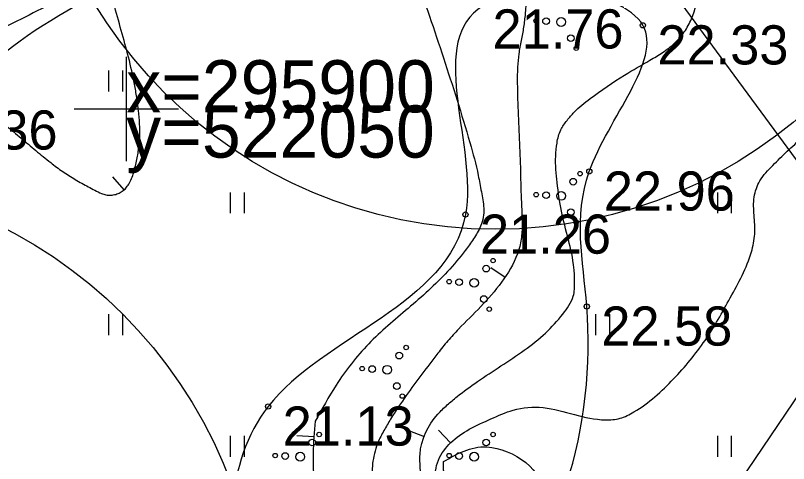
# Model space of a CAD drawing. Extents: x 521824 to 524158, y 294774 to 296228.
# Drawn here: x 522046.82 to 522069.04, y 295889.8 to 295902.69 of the extents above; entities that cross this region are included whole.
import ezdxf

# ---------------------------------------------------------------- set-up
doc = ezdxf.new("R2010")
doc.units = 0
for name, color, linetype in [('CELI_TAKA_####_####_#', 7, 'Continuous'), ('GEOD_ELEM_####_####_#', 7, 'Continuous'), ('GEOD_KORD_####_TKST_#', 7, 'Continuous'), ('Geolite Projekts', 7, 'Continuous'), ('GL Aizsargjoslas', 7, 'Continuous'), ('RELJ_AATZ_####_TKST_#', 7, 'Continuous'), ('RELJ_ELEM_####_####_#', 7, 'Continuous'), ('RELJ_HORZ_PAMT_####_#', 7, 'Continuous'), ('RELJ_HORZ_RESN_####_#', 7, 'Continuous'), ('RELJ_NOGA_####_####_#', 7, 'Continuous'), ('RELJ_NOGL_####_####_#', 7, 'Continuous'), ('TERT_ELEM_####_####_#', 7, 'Continuous'), ('TERT_KONT_####_####_#', 7, 'Continuous')]:
    doc.layers.add(name, color=color, linetype=linetype)

msp = doc.modelspace()

# ---------------------------------------------------------------- linework, layer by layer
at = {"layer": 'CELI_TAKA_####_####_#'}
msp.add_lwpolyline([(522095.856, 295905.56700000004), (522084.37100000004, 295904.45), (522075.74700000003, 295894.91500000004), (522069.03400000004, 295885.9050000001), (522061.956, 295874.973), (522056.367, 295864.379), (522051.5294335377, 295852.1437104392), (522046.912, 295851.297), (522038.77300000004, 295857.478), (522034.27400000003, 295863.827), (522038.98455083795, 295867.1660796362), (522042.3269003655, 295865.914968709), (522049.35500000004, 295864.324), (522054.37200000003, 295869.372), (522059.47900000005, 295876.809), (522066.34400000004, 295887.376), (522073.29600000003, 295897.65400000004), (522079.21, 295907.668), (522079.60400000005, 295917.159)], dxfattribs=at)
at = {"layer": 'GEOD_ELEM_####_####_#'}
for p, q in [((522050, 295901.5), (522050, 295900)), ((522048.5, 295900), (522050, 295900)), ((522050, 295900), (522050, 295898.5)), ((522050, 295900), (522051.5, 295900))]:
    msp.add_line(p, q, dxfattribs=at)
at = {"layer": 'Geolite Projekts'}
for centre in [(522060.6062488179, 295910.0052488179), (522040.37824881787, 295884.5782488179)]:
    msp.add_circle(centre, 13.465789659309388, dxfattribs=at)
at = {"layer": 'GL Aizsargjoslas'}
msp.add_lwpolyline([(522131.42829998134, 295816.08118555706), (522115.4941642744, 295836.89638272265), (522093.2463759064, 295865.95927699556), (522070.6576329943, 295896.65064863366), (522048.0688900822, 295927.34202027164), (522034.2954443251, 295950.9093556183), (522016.4452583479, 295981.4522804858), (522014.1669435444, 295985.3506375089), (522007.1170540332, 295997.9066058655), (522041.3600169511, 296024.30747637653), (522061.8608109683, 296026.336216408), (522066.44900074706, 296014.80384880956), (522085.297555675, 295982.5526443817), (522098.68966425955, 295959.6378037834), (522141.23362409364, 295901.9807230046), (522163.3093357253, 295873.1426172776), (522185.385047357, 295844.30451155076), (522186.60753180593, 295842.8705587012), (522172.84800000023, 295833.39200000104), (522161.56349999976, 295826.06900000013), (522160.80220084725, 295825.5718620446), (522154.44700000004, 295832.01500000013)], close=True, dxfattribs=at)
at = {"layer": 'RELJ_ELEM_####_####_#'}
for centre in [(522064.85000000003, 295902.40400000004), (522063.309, 295898.202), (522059.75, 295896.963), (522063.237, 295894.32), (522054.07800000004, 295891.445)]:
    msp.add_circle(centre, 0.075, dxfattribs=at)
at = {"layer": 'RELJ_HORZ_PAMT_####_#'}
for p, q in [((522049.60648515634, 295898.0477462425), (522049.9331036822, 295897.66916951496)), ((522054.9032718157, 295890.6113446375), (522055.4021474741, 295890.57783229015)), ((522058.0958806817, 295890.76675691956), (522058.5617377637, 295890.5851607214)), ((522058.9771039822, 295890.76097983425), (522059.31931511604, 295890.39643691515))]:
    msp.add_line(p, q, dxfattribs=at)
for points in [[(522066.2584823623, 295871.9491597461), (522065.9265126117, 295872.02069348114), (522065.52187982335, 295872.1924293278), (522064.7111958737, 295872.77815327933), (522063.9034044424, 295873.5790320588), (522063.5023873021, 295874.01971144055), (522063.1042459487, 295874.4656478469), (522062.71785695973, 295875.16654893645), (522062.57713892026, 295875.4946600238), (522062.27065971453, 295876.0108950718), (522061.9020967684, 295876.4975825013), (522061.55203381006, 295876.9935582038), (522061.30105456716, 295877.5376580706), (522061.20400779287, 295877.93591094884), (522061.12801898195, 295878.33525191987), (522061.0351401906, 295879.1357661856), (522061.0142680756, 295879.93633695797), (522061.05725251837, 295880.73410032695), (522061.2405002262, 295882.3468136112), (522061.4726604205, 295883.9570245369), (522061.59669191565, 295884.54701605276), (522061.5847127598, 295884.58544792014), (522061.17685574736, 295885.2867575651), (522060.72233918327, 295885.9348866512), (522060.2601026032, 295886.5684557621), (522059.82908554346, 295887.2260854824), (522059.0920299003, 295888.55811252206), (522058.89348460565, 295889.2513533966), (522058.8913293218, 295889.5862413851), (522058.97472722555, 295889.90624515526), (522059.32943879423, 295890.4058551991), (522059.8583838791, 295890.78845924), (522060.4810182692, 295891.08831341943), (522061.11679775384, 295891.3396738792), (522061.9816911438, 295891.4141705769), (522062.8825577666, 295891.21225084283), (522063.7697265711, 295891.0611807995), (522064.1926520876, 295891.1069850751), (522064.5935265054, 295891.2882265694), (522065.73111615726, 295892.2383905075), (522066.63585033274, 295893.34363634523), (522067.3630420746, 295894.5711369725), (522067.9680044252, 295895.88806527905), (522068.0658538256, 295896.40279857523), (522068.04657160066, 295896.9434330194), (522068.0499213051, 295897.4675584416), (522068.21566649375, 295897.9327646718), (522068.58369240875, 295898.3767775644), (522068.99960998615, 295898.782723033), (522069.42179390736, 295899.1843208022), (522069.8086188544, 295899.61529059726), (522071.07609156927, 295901.3045079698), (522072.2197685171, 295903.14131751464), (522073.0777767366, 295905.1256097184), (522073.6055682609, 295907.1854540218), (522073.837089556, 295909.2646973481), (522073.85235713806, 295910.2940458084), (522073.8062870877, 295911.3071866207), (522073.4235574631, 295912.99914973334), (522073.02667042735, 295913.81930856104), (522072.479111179, 295914.61778212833), (522071.01685177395, 295916.0448324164), (522069.31251789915, 295917.0118651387), (522068.5372975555, 295917.2378305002), (522065.5425407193, 295917.72990654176), (522064.0452324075, 295917.74536597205), (522063.3144481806, 295917.64344913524), (522062.6023781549, 295917.4486243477), (522062.2001250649, 295917.20845970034), (522060.8816914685, 295916.59798905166)], [(522059.84382235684, 295885.48121856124), (522059.8438223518, 295885.4812185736), (522059.78676631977, 295885.6171710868), (522058.8865142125, 295887.8562219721), (522058.55276315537, 295888.9834516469), (522058.46311323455, 295889.53502410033), (522058.4436111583, 295889.80605367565), (522058.4432829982, 295890.0732469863), (522058.95354503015, 295891.22221891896), (522059.2266140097, 295891.4889343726), (522059.5078144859, 295891.7280506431), (522060.0974200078, 295892.16235402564), (522061.4403651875, 295893.0655420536), (522062.05069449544, 295893.5569964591), (522062.5478378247, 295894.10367275), (522062.84795303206, 295894.6148813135), (522062.8876709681, 295895.02128771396), (522062.86697334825, 295895.42851699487), (522062.7095877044, 295896.24487815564), (522062.5063086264, 295897.06283271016), (522062.3876486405, 295897.88124857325), (522062.34300690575, 295898.6402559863), (522062.38142149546, 295899.0201946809), (522062.4892913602, 295899.3960738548), (522062.67100015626, 295899.6700522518), (522062.87542367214, 295899.9064522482), (522063.33430111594, 295900.2977858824), (522064.3253814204, 295900.9734696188), (522065.0535739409, 295901.4006113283), (522065.4168611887, 295901.62440442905), (522065.59205733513, 295901.74880483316), (522065.7622515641, 295901.8909530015), (522066.0402461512, 295902.2124144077), (522066.24466940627, 295902.5881278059), (522066.4460868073, 295903.44091490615), (522066.27945845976, 295904.74326254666), (522066.11219937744, 295905.1221606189), (522065.4824909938, 295906.23163838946), (522064.81863151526, 295907.3324170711), (522064.15650249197, 295908.43747979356), (522063.5319854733, 295909.5598096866), (522062.8487309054, 295910.87969144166), (522062.23551999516, 295912.2254142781), (522061.55132910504, 295913.5372971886), (522060.6551345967, 295914.7556591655)], [(522056.1793664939, 295908.1153325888), (522056.48434317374, 295907.6743405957), (522056.8475368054, 295907.0795841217), (522057.17609128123, 295906.4660634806), (522057.4766860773, 295905.8230094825), (522057.76204092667, 295905.1745785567), (522058.2862568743, 295903.85904208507), (522058.71639752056, 295902.66520022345), (522059.118007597, 295901.46666925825), (522059.876249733, 295899.0317423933), (522060.11747807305, 295898.0904908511), (522060.20674188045, 295897.61826545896), (522060.27568828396, 295897.14600863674), (522060.18688952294, 295896.63185604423), (522060.09080228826, 295896.43995465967), (522059.9849630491, 295896.2639437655), (522059.74596148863, 295895.9336084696), (522059.2350731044, 295895.323283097), (522058.0985815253, 295894.2628950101), (522056.967747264, 295893.243683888), (522056.03290279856, 295892.0586418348), (522055.4318217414, 295891.019573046)], [(522044.3960820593, 295900.93691802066), (522044.4961399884, 295900.8916618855), (522044.8780289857, 295900.71492382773), (522045.2798363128, 295900.47416145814), (522046.1231182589, 295899.85556856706), (522046.5540807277, 295899.51268228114), (522046.9768135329, 295899.1602485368), (522047.39885349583, 295898.80536858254), (522047.827737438, 295898.45514366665), (522048.17397656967, 295898.2006330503), (522048.53616659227, 295897.970216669), (522048.9093562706, 295897.7610938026), (522049.09852871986, 295897.6636422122), (522049.2885943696, 295897.5704637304), (522049.4174768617, 295897.5294679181), (522049.55699419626, 295897.5208775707), (522049.69695640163, 295897.54360238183), (522049.82717350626, 295897.5965520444), (522049.93918509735, 295897.6744915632), (522050.03092400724, 295897.77483245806), (522050.11421739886, 295897.91129787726), (522050.18428589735, 295898.08160530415), (522050.28305070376, 295898.4529787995), (522050.3526554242, 295898.8248105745), (522050.38413350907, 295899.56810806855), (522050.35036100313, 295899.9499198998), (522050.301222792, 295900.33172656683), (522050.2371131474, 295900.7133025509), (522050.15842634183, 295901.09442233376), (522049.9618199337, 295901.8739762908), (522049.74695353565, 295902.6432265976), (522049.54332001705, 295903.41224045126), (522049.3804122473, 295904.1910850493)], [(522055.4318217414, 295891.019573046), (522055.37014606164, 295890.1014488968), (522055.4470548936, 295888.9609942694), (522055.7296555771, 295887.83428687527), (522056.06387243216, 295886.7113670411), (522056.2956297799, 295885.5822750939), (522056.3400053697, 295884.7079058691), (522056.29896105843, 295883.8276911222), (522056.21917381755, 295882.9659028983), (522056.0627431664, 295882.1126921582), (522055.74228698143, 295881.31167885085), (522055.4932424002, 295880.9443774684), (522055.34173727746, 295880.77141356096), (522055.17042313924, 295880.6064829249), (522053.57967248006, 295879.6908835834), (522051.9053664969, 295879.14560185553), (522050.9940921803, 295878.8470417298), (522050.07542193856, 295878.5759373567), (522049.16184283, 295878.2965748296), (522048.2658419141, 295877.97324024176), (522047.5623538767, 295877.5852288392), (522046.9168776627, 295877.09137443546), (522046.27015451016, 295876.584014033), (522045.5629256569, 295876.1554846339), (522043.6590880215, 295875.4747996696), (522042.6881821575, 295875.24141524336), (522041.71527555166, 295875.04061326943), (522040.9641437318, 295875.0354235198), (522040.19584451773, 295875.1907002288), (522039.43001499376, 295875.32124058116), (522039.0541629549, 295875.31935874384), (522038.68629224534, 295875.24184176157), (522038.09173308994, 295874.7908192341), (522037.69889233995, 295874.0857750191), (522037.32043209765, 295873.3281628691), (522036.76901446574, 295872.7194365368), (522036.4041626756, 295872.46231910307), (522036.02899815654, 295872.18553573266), (522035.2625355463, 295871.6712335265), (522034.4992358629, 295871.37305460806), (522033.76870833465, 295871.4875236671), (522032.7232997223, 295872.0869174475), (522032.2844500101, 295872.36637101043), (522031.8459632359, 295872.6828132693), (522030.97087213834, 295873.339843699), (522030.09961370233, 295873.88436838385), (522029.66591775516, 295874.0601784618), (522029.44963990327, 295874.1144744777), (522029.3416543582, 295874.1320332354), (522029.2877012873, 295874.1382669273), (522029.2337752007, 295874.14274697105), (522028.85008152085, 295874.04160905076), (522028.5912106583, 295873.7133159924), (522028.3693924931, 295872.5875977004), (522028.4112309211, 295871.19025857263), (522028.5596361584, 295869.94596508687), (522028.86549492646, 295868.4799487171), (522029.36778649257, 295867.02795840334), (522029.58666482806, 295866.6532661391), (522029.8605808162, 295866.31675508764), (522030.1297951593, 295865.98190621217), (522030.3345685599, 295865.6122004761), (522030.4260470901, 295863.3276212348), (522030.1984270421, 295862.6546480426), (522029.93107295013, 295861.99170752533), (522029.61666622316, 295861.34511401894), (522029.24788827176, 295860.7211818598), (522028.9410967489, 295860.282200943), (522028.6200155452, 295859.86198979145), (522028.29579766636, 295859.44523702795), (522027.9795961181, 295859.01663127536), (522026.69170504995, 295857.52527430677), (522026.2760502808, 295856.7875150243), (522026.2678256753, 295856.4558827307), (522026.44696676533, 295856.16251725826), (522027.1481473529, 295855.54097012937), (522027.87851884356, 295854.9286336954)], [(522059.12000000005, 295889.86), (522059.1215262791, 295889.61773891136), (522059.865566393, 295888.61303305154), (522060.4507352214, 295888.0002889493), (522061.9358427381, 295888.90778682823), (522060.3652014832, 295890.2831699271), (522059.12000000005, 295889.86)]]:
    msp.add_spline(points, degree=3, dxfattribs=at)
at = {"layer": 'RELJ_HORZ_RESN_####_#'}
msp.add_line((522060.4750291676, 295895.4383529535), (522060.8894894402, 295895.1586697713), dxfattribs=at)
msp.add_spline([(522061.48667825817, 295905.01216273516), (522061.5051203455, 295903.71652376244), (522061.4658982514, 295902.7309870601), (522061.4199592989, 295902.3496912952), (522061.3493716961, 295901.9690333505), (522061.28254781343, 295901.5877092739), (522061.2479000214, 295901.2044151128), (522061.2503854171, 295900.2841077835), (522061.28468994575, 295899.3628132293), (522061.3259081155, 295898.44114310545), (522061.3491344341, 295897.51970906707), (522061.37899848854, 295896.6741732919), (522061.3515134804, 295896.2523423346), (522061.3094520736, 295896.04204503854), (522061.2417629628, 295895.8323061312), (522060.7859516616, 295895.01471247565), (522060.1914302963, 295894.3204045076), (522059.5504158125, 295893.6679518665), (522059.2412914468, 295893.331974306), (522058.95512515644, 295892.975924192), (522058.047028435, 295891.7563603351), (522057.62349787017, 295891.1238069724), (522057.4294407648, 295890.7925941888), (522057.2510286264, 295890.44790276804), (522057.15050354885, 295890.1616023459), (522057.09076180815, 295889.873450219), (522057.0795902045, 295889.2968197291), (522057.19438158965, 295888.4923322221)], degree=3, dxfattribs=at)
at = {"layer": 'RELJ_NOGA_####_####_#'}
msp.add_spline([(522051.0088986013, 295908.7681172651), (522050.955, 295908.62100000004), (522050.8544228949, 295908.146692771), (522050.82150032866, 295907.9060559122), (522050.7741314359, 295907.6687359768), (522050.5203801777, 295906.7334970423), (522050.2041888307, 295905.8140095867), (522049.836, 295904.909), (522049.3106596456, 295904.10918949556), (522048.56891222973, 295903.4733838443), (522046.74113339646, 295902.46909768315), (522044.9625378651, 295901.44676268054), (522044.2822695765, 295900.7883959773), (522043.84300000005, 295899.957), (522043.5061490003, 295898.8223678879), (522043.2032403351, 295897.68297782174), (522042.68963733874, 295895.3900866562), (522042.2829656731, 295893.0786521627), (522041.96400000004, 295890.749), (522041.85628049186, 295889.94464635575), (522041.7344421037, 295889.14043252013), (522041.49427188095, 295887.53206102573), (522041.34900000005, 295884.313), (522041.75700000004, 295879.287)], degree=3, dxfattribs=at)
at = {"layer": 'RELJ_NOGL_####_####_#'}
msp.add_spline([(522041.75700000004, 295879.287), (522039.992, 295882.845), (522040.66500000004, 295887.209), (522041.3229999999, 295899.54), (522046.69200000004, 295904.034), (522047.90400000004, 295911.24600000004), (522051.803, 295923.738), (522047.81600000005, 295927.907), (522041.71599861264, 295918.50505158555), (522040.412, 295917.353), (522035.97000000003, 295918.376)], degree=3, dxfattribs=at)
at = {"layer": 'TERT_ELEM_####_####_#'}
for p, q in [((522049.5, 295900.5), (522049.5, 295901.10000000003)), ((522049.9, 295900.5), (522049.9, 295901.10000000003)), ((522056.5, 295900.5), (522056.5, 295901.10000000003)), ((522056.9, 295900.5), (522056.9, 295901.10000000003)), ((522053, 295897), (522053, 295897.60000000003)), ((522053.4, 295897), (522053.4, 295897.60000000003)), ((522067, 295897), (522067, 295897.60000000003)), ((522067.4, 295897), (522067.4, 295897.60000000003)), ((522049.5, 295893.5), (522049.5, 295894.10000000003)), ((522049.9, 295893.5), (522049.9, 295894.10000000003)), ((522063.5, 295893.5), (522063.5, 295894.10000000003)), ((522063.9, 295893.5), (522063.9, 295894.10000000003)), ((522053, 295890), (522053, 295890.60000000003)), ((522053.4, 295890), (522053.4, 295890.60000000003)), ((522067, 295890), (522067, 295890.60000000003)), ((522067.4, 295890), (522067.4, 295890.60000000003))]:
    msp.add_line(p, q, dxfattribs=at)
for centre, radius in [((522061.78160000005, 295902.53423999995), 0.06400000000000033), ((522062.06608, 295902.52079999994), 0.09600000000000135), ((522062.5, 295902.5), 0.12800000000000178), ((522062.77647999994, 295902.0331199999), 0.09600000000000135), ((522062.93392, 295901.74383999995), 0.06400000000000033), ((522063.04400000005, 295898.13936), 0.06400000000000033), ((522062.84752, 295897.90767999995), 0.09600000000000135), ((522061.78160000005, 295897.53423999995), 0.06400000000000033), ((522062.06608, 295897.52079999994), 0.09600000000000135), ((522062.5, 295897.5), 0.12800000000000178), ((522062.77647999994, 295897.0331199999), 0.09600000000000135), ((522062.93392, 295896.74383999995), 0.06400000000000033), ((522060.54400000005, 295895.63936), 0.06400000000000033), ((522060.34752, 295895.40767999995), 0.09600000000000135), ((522059.28160000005, 295895.03423999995), 0.06400000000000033), ((522059.56608, 295895.02079999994), 0.09600000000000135), ((522060, 295895), 0.12800000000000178), ((522060.27647999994, 295894.5331199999), 0.09600000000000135), ((522060.43392, 295894.24383999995), 0.06400000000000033), ((522058.04400000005, 295893.13936), 0.06400000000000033), ((522057.84752, 295892.90767999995), 0.09600000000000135), ((522056.78160000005, 295892.53423999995), 0.06400000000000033), ((522057.06608, 295892.52079999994), 0.09600000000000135), ((522057.5, 295892.5), 0.12800000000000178), ((522057.77647999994, 295892.0331199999), 0.09600000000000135), ((522057.93392, 295891.74383999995), 0.06400000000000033), ((522055.54400000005, 295890.63936), 0.06400000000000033), ((522060.54400000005, 295890.63936), 0.06400000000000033), ((522055.34752, 295890.40767999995), 0.09600000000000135), ((522060.34752, 295890.40767999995), 0.09600000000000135), ((522054.28160000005, 295890.03423999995), 0.06400000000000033), ((522054.56608, 295890.02079999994), 0.09600000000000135), ((522055, 295890), 0.12800000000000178), ((522059.28160000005, 295890.03423999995), 0.06400000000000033), ((522059.56608, 295890.02079999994), 0.09600000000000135), ((522060, 295890), 0.12800000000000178)]:
    msp.add_circle(centre, radius, dxfattribs=at)
at = {"layer": 'TERT_KONT_####_####_#'}
for points in [[(522059.44160099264, 295917.88252916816), (522069.8456781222, 295914.579867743), (522070.92833589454, 295913.23238188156), (522059.2831632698, 295914.31565482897), (522058.19390392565, 295914.31565482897), (522056.2068308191, 295906.64026967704), (522054.275, 295906.0520000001), (522050.3842445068, 295904.00474585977), (522046.7335753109, 295901.7853573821), (522044.3306031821, 295899.1498335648), (522041.823697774, 295889.72399833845), (522041.823697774, 295881.1995209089), (522041.75700000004, 295879.287)], [(522041.75700000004, 295879.287), (522039.8510524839, 295883.2337945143), (522039.8510524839, 295886.0580836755), (522040.98056279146, 295896.720775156), (522040.98056279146, 295900.05971678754), (522046.0882716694, 295903.28311433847), (522046.8540539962, 295907.74831258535), (522047.619836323, 295911.76434887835), (522048.3063997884, 295913.9308947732), (522038.0079478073, 295914.53858447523), (522030.69340627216, 295913.5874179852), (522024.59190355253, 295911.91627130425), (522021.05961908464, 295904.1580703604), (522010.60152255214, 295892.09204609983), (522007.315, 295893.1280000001)], [(522052.97500000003, 295885.195), (522054.07800000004, 295891.445), (522059.75, 295896.963), (522060.11000000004, 295902.862), (522064.85000000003, 295902.40400000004), (522063.309, 295898.202), (522063.237, 295894.32), (522059.78400000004, 295885.512), (522058.72631464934, 295884.9836287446), (522057.081, 295883.506), (522052.97500000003, 295885.195)]]:
    msp.add_spline(points, degree=3, dxfattribs=at)

# ---------------------------------------------------------------- texts
at = {"layer": 'GEOD_KORD_####_TKST_#'}
for s, p in [('x=295900', (522050, 295899.9)), ('y=522050', (522050, 295898.60000000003))]:
    msp.add_text(s, height=1.5, dxfattribs=at).set_placement(p)
at = {"layer": 'RELJ_AATZ_####_TKST_#'}
for s, p in [(' 21.76', (522060.11000000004, 295901.737)), (' 22.33', (522064.85000000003, 295901.27900000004)), (' 21.36', (522043.84300000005, 295898.832)), (' 22.96', (522063.309, 295897.077)), (' 21.26', (522059.75, 295895.838)), (' 22.58', (522063.237, 295893.195)), (' 21.13', (522054.07800000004, 295890.32))]:
    msp.add_text(s, height=1.125, dxfattribs=at).set_placement(p)

doc.saveas('drawing.dxf')
